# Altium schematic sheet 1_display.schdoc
size 307 x 218 mm; Symbol: Drawing-Symbol_A4; Device: Drawing-Symbol_A4; @Project Name: Chaoticvolt-4 digit 7seg display; @Page Count: 1; @Update Date: 2025-02-28; @Create Date: 2025-02-28; @Schematic Name: 4 digit 7seg display; @Page No: 1; @Page Name: display; Company: EasyEDA.com; Version: V2.0; Page Size: A4; @Create Time: 15:44:37; @Update Time: 17:22:36; Width: 1170; Height: 825; Region Start: 1; X Region Count: 6; Y Region Count: 4; Blade Width: 10; Title Block Position: 3; @Board Name: 4 digit 7seg display
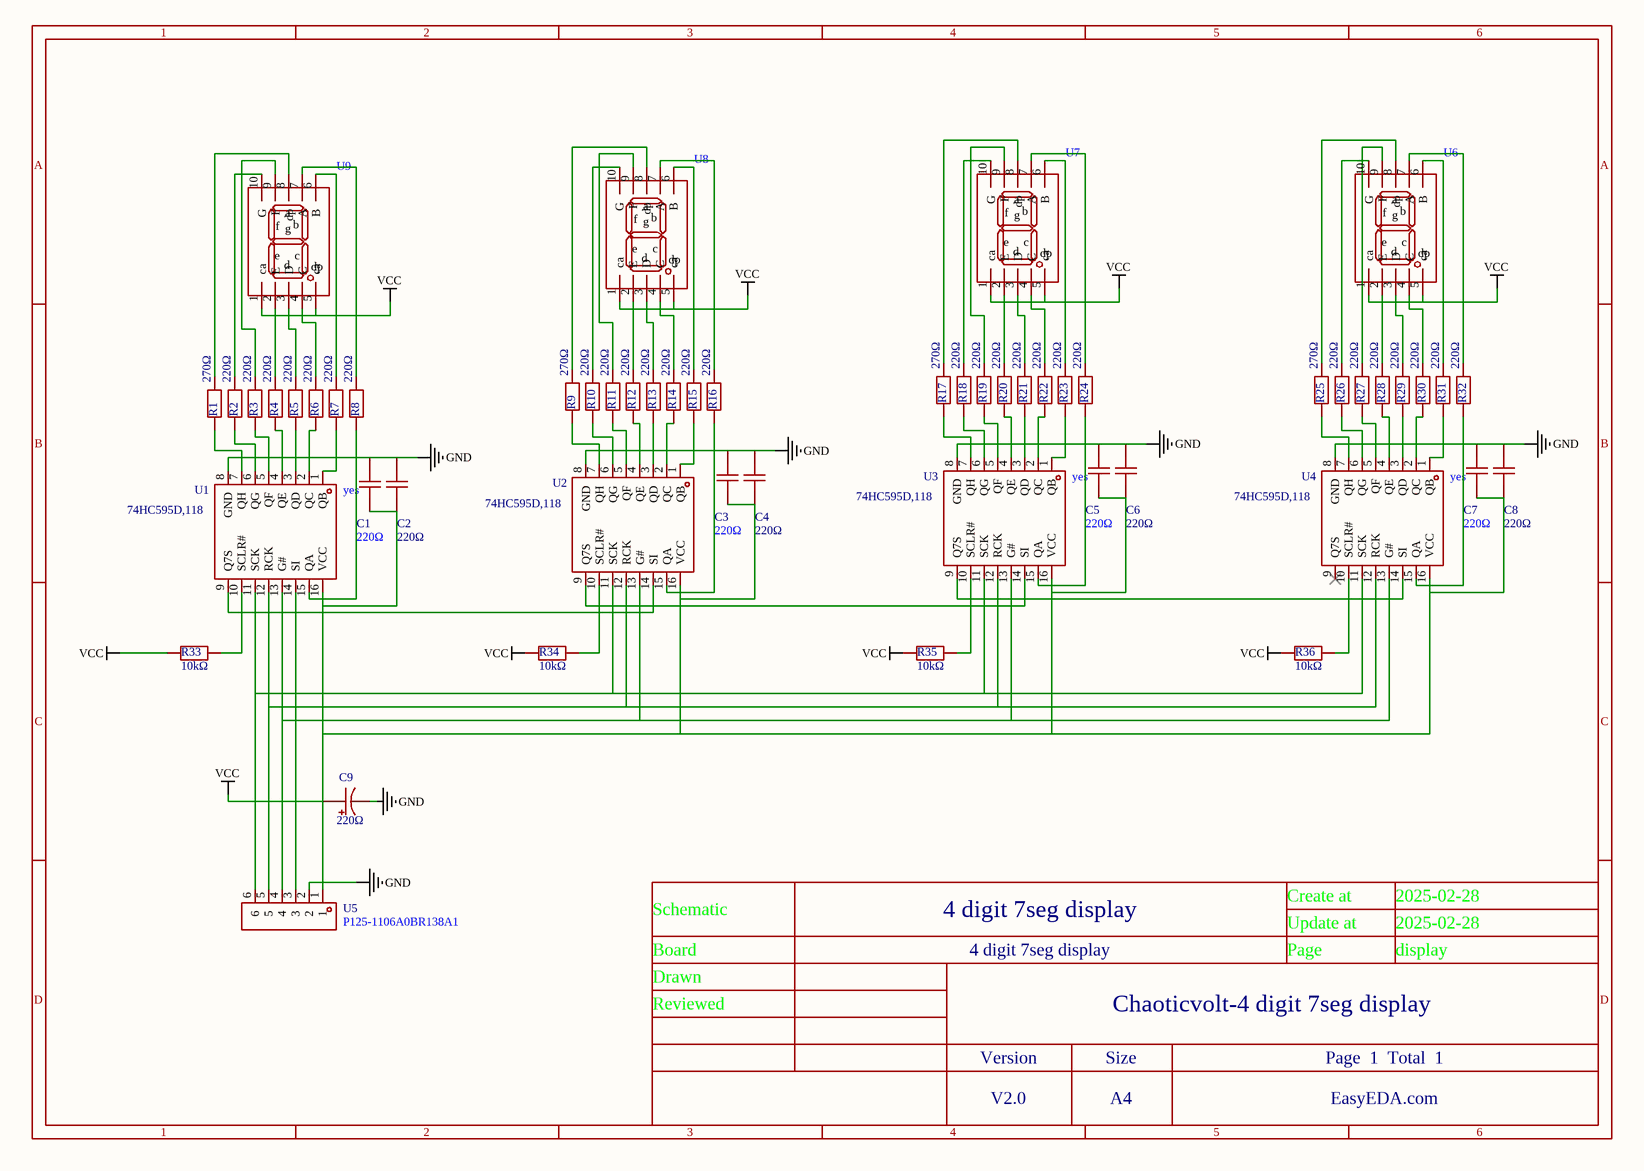
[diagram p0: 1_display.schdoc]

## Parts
C1  220Ω  [R0805]
C2  220Ω  [R0805]
C3  220Ω  [R0805]
C4  220Ω  [R0805]
C5  220Ω  [R0805]
C6  220Ω  [R0805]
C7  220Ω  [R0805]
C8  220Ω  [R0805]
C9  220Ω  [R0805]
R1  270Ω  [R0805]
R2  220Ω  [R0805]
R3  220Ω  [R0805]
R4  220Ω  [R0805]
R5  220Ω  [R0805]
R6  220Ω  [R0805]
R7  220Ω  [R0805]
R8  220Ω  [R0805]
R9  270Ω  [R0805]
R10  220Ω  [R0805]
R11  220Ω  [R0805]
R12  220Ω  [R0805]
R13  220Ω  [R0805]
R14  220Ω  [R0805]
R15  220Ω  [R0805]
R16  220Ω  [R0805]
R17  270Ω  [R0805]
R18  220Ω  [R0805]
R19  220Ω  [R0805]
R20  220Ω  [R0805]
R21  220Ω  [R0805]
R22  220Ω  [R0805]
R23  220Ω  [R0805]
R24  220Ω  [R0805]
R25  270Ω  [R0805]
R26  220Ω  [R0805]
R27  220Ω  [R0805]
R28  220Ω  [R0805]
R29  220Ω  [R0805]
R30  220Ω  [R0805]
R31  220Ω  [R0805]
R32  220Ω  [R0805]
R33  10kΩ  [R0805]
R34  10kΩ  [R0805]
R35  10kΩ  [R0805]
R36  10kΩ  [R0805]
U1  74HC595D,118  Add into BOM: yes  [SOIC-16_L9.9-W3.9-P1.27-LS6.0-BL]
U2  74HC595D,118  [SOIC-16_L9.9-W3.9-P1.27-LS6.0-BL]
U3  74HC595D,118  Add into BOM: yes  [SOIC-16_L9.9-W3.9-P1.27-LS6.0-BL]
U4  74HC595D,118  Add into BOM: yes  [SOIC-16_L9.9-W3.9-P1.27-LS6.0-BL]
U5  P125-1106A0BR138A1  [HDR-TH_6P-P2.54-H-M_P125-1106A0BR138A1]
U6  (no value)  [FJS12101]
U7  (no value)  [FJS12101]
U8  (no value)  [FJS12101]
U9  (no value)  [FJS12101]

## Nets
GND: C1.2 C2.2 C3.2 C4.2 C5.2 C6.2 C7.2 C8.2 C9.2 U1.8(GND) U2.8(GND) U3.8(GND) U4.8(GND) U5.2
VCC: C1.1 C2.1 C3.1 C4.1 C5.1 C6.1 C7.1 C8.1 C9.1 R33.2 R34.2 R35.2 R36.2 U1.16(VCC) U2.16(VCC) U3.16(VCC) U4.16(VCC) U5.1 U6.1(ca) U6.5(ca) U7.1(ca) U7.5(ca) U8.1(ca) U8.5(ca) U9.1(ca) U9.5(ca)
NetR1_1: R1.1 U9.8(dp)
NetR1_2: R1.2 U1.7(QH)
NetR2_1: R2.1 U9.10(G)
NetR2_2: R2.2 U1.6(QG)
NetR3_1: R3.1 U9.9(F)
NetR3_2: R3.2 U1.5(QF)
NetR4_1: R4.1 U9.2(E)
NetR4_2: R4.2 U1.4(QE)
NetR5_1: R5.1 U9.3(D)
NetR5_2: R5.2 U1.3(QD)
NetR6_1: R6.1 U9.4(C)
NetR6_2: R6.2 U1.2(QC)
NetR7_1: R7.1 U9.6(B)
NetR7_2: R7.2 U1.1(QB)
NetR8_1: R8.1 U9.7(A)
NetR8_2: R8.2 U1.15(QA)
NetR9_1: R9.1 U8.8(dp)
NetR9_2: R9.2 U2.7(QH)
NetR10_1: R10.1 U8.10(G)
NetR10_2: R10.2 U2.6(QG)
NetR11_1: R11.1 U8.9(F)
NetR11_2: R11.2 U2.5(QF)
NetR12_1: R12.1 U8.2(E)
NetR12_2: R12.2 U2.4(QE)
NetR13_1: R13.1 U8.3(D)
NetR13_2: R13.2 U2.3(QD)
NetR14_1: R14.1 U8.4(C)
NetR14_2: R14.2 U2.2(QC)
NetR15_1: R15.1 U8.6(B)
NetR15_2: R15.2 U2.1(QB)
NetR16_1: R16.1 U8.7(A)
NetR16_2: R16.2 U2.15(QA)
NetR17_1: R17.1 U7.8(dp)
NetR17_2: R17.2 U3.7(QH)
NetR18_1: R18.1 U7.10(G)
NetR18_2: R18.2 U3.6(QG)
NetR19_1: R19.1 U7.9(F)
NetR19_2: R19.2 U3.5(QF)
NetR20_1: R20.1 U7.2(E)
NetR20_2: R20.2 U3.4(QE)
NetR21_1: R21.1 U7.3(D)
NetR21_2: R21.2 U3.3(QD)
NetR22_1: R22.1 U7.4(C)
NetR22_2: R22.2 U3.2(QC)
NetR23_1: R23.1 U7.6(B)
NetR23_2: R23.2 U3.1(QB)
NetR24_1: R24.1 U7.7(A)
NetR24_2: R24.2 U3.15(QA)
NetR25_1: R25.1 U6.8(dp)
NetR25_2: R25.2 U4.7(QH)
NetR26_1: R26.1 U6.10(G)
NetR26_2: R26.2 U4.6(QG)
NetR27_1: R27.1 U6.9(F)
NetR27_2: R27.2 U4.5(QF)
NetR28_1: R28.1 U6.2(E)
NetR28_2: R28.2 U4.4(QE)
NetR29_1: R29.1 U6.3(D)
NetR29_2: R29.2 U4.3(QD)
NetR30_1: R30.1 U6.4(C)
NetR30_2: R30.2 U4.2(QC)
NetR31_1: R31.1 U6.6(B)
NetR31_2: R31.2 U4.1(QB)
NetR32_1: R32.1 U6.7(A)
NetR32_2: R32.2 U4.15(QA)
NetR33_1: R33.1 U1.10(SCLR#)
NetR34_1: R34.1 U2.10(SCLR#)
NetR35_1: R35.1 U3.10(SCLR#)
NetR36_1: R36.1 U4.10(SCLR#)
NetU1_9: U1.9(Q7S) U2.14(SI)
NetU1_11: U1.11(SCK) U2.11(SCK) U3.11(SCK) U4.11(SCK) U5.6
NetU1_12: U1.12(RCK) U2.12(RCK) U3.12(RCK) U4.12(RCK) U5.5
NetU1_13: U1.13(G#) U2.13(G#) U3.13(G#) U4.13(G#) U5.4
NetU1_14: U1.14(SI) U5.3
NetU2_9: U2.9(Q7S) U3.14(SI)
NetU3_9: U3.9(Q7S) U4.14(SI)

Not connected (* = marked no-connect by the designer): U4 9(Q7S)*

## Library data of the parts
C1 C3 C5 C7 = CR0805J80221G: Manufacturer: LIZ(丽智电子); Symbol: CL31A476MPHNNNE; Add into BOM: yes; Type: Thick Film Resistors; Tolerance: ±5%; Temperature Coefficient: ±200ppm/℃
C2 C4 C6 C8 = CR0805J80221G: Manufacturer: LIZ(丽智电子); Symbol: C1210C104K1RAC7800; Add into BOM: yes; Type: Thick Film Resistors; Tolerance: ±5%; Temperature Coefficient: ±200ppm/℃
C9 = CR0805J80221G: Manufacturer: LIZ(丽智电子); Symbol: CA45-B-10V-100UF-M; Add into BOM: yes; Type: Thick Film Resistors; Tolerance: ±5%; Temperature Coefficient: ±200ppm/℃
R1 R9 R17 R25 = CR0805J80271G: Manufacturer: LIZ(丽智电子); Symbol: RK73H2ETTD2700F; Add into BOM: yes; Tolerance: ±5%; Temperature Coefficient: ±200ppm/℃
R2-R8 R10-R16 R18-R24 R26-R32 = CR0805J80221G: Manufacturer: LIZ(丽智电子); Symbol: RK73H2ETTD2700F; Add into BOM: yes; Tolerance: ±5%; Temperature Coefficient: ±200ppm/℃
R33-R36 = CR0805F81002G: Manufacturer: LIZ(丽智电子); Symbol: RK73H2ETTD1002F; Add into BOM: yes; Tolerance: ±1%; Temperature Coefficient: ±100ppm/℃
U1 U3 U4 = 74HC595D,118: Manufacturer: Nexperia(安世); Symbol: 74HC595D_C431479; Logic Type: ShiftRegister; Output Type: Tri-State; Function: Serial to parallel, serial; Voltage - Supply: 2V~6V
U2 = 74HC595D,118: Manufacturer: Nexperia(安世); Symbol: 74HC595D_C431479; Add into BOM: yes; Logic Type: ShiftRegister; Output Type: Tri-State; Function: Serial to parallel, serial; Voltage - Supply: 2V~6V
U5 = P125-1106A0BR138A1: Manufacturer: Yxcon(宇熙精密); Add into BOM: yes; Pin Structure: 1x6P; Pitch: 2.54mm; Circluar Pins/Square Pins: Policy
U6-U9 = FJS12101: Add into BOM: yes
